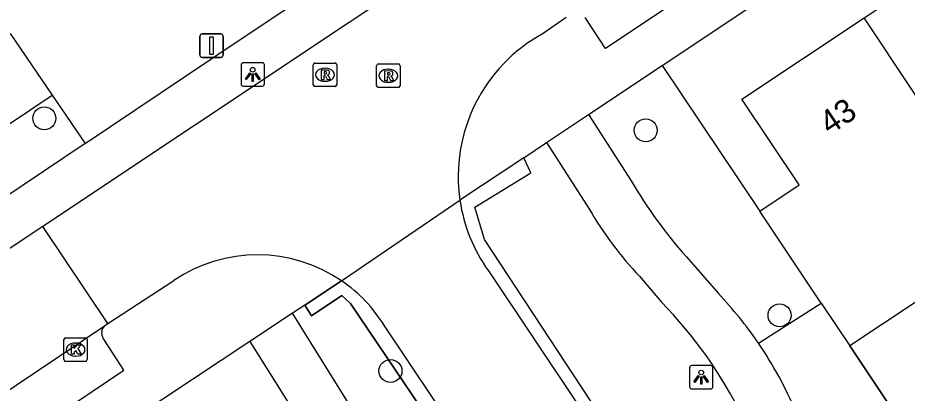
# Model space of a CAD drawing. Extents: x 158352 to 159489, y 383828 to 384597.
# Drawn here: x 158685.53 to 158723.41, y 384360.5 to 384376.52 of the extents above; entities that cross this region are included whole.
import ezdxf

# ---------------------------------------------------------------- set-up
doc = ezdxf.new("R2010")
doc.units = 0
for name, color, linetype in [('IMGEO_Boom', 7, 'Continuous'), ('IMGEO_Groenvoorziening', 7, 'Continuous'), ('IMGEO_Haag', 7, 'Continuous'), ('IMGEO_Kolk', 7, 'Continuous'), ('IMGEO_Lichtpunt', 7, 'Continuous'), ('IMGEO_Muur', 7, 'Continuous'), ('IMGEO_Pand', 7, 'Continuous'), ('IMGEO_Pand_nummerreeks', 7, 'Continuous'), ('IMGEO_Rijbaan_lokaal_open', 7, 'Continuous'), ('IMGEO_Rioolput', 7, 'Continuous'), ('IMGEO_Verkeersbordpaal', 7, 'Continuous'), ('IMGEO_Voetpad_gesloten', 7, 'Continuous'), ('IMGEO_Voetpad_open', 7, 'Continuous')]:
    doc.layers.add(name, color=color, linetype=linetype)

msp = doc.modelspace()

# ---------------------------------------------------------------- linework, layer by layer
at = {"layer": 'IMGEO_Boom'}
for centre in [(158686.653, 384372.225), (158712.272, 384371.717), (158717.972, 384363.823), (158701.4, 384361.451)]:
    msp.add_circle(centre, 0.489, dxfattribs=at)
at = {"layer": 'IMGEO_Groenvoorziening'}
for points in [[(158643.13, 384347.868), (158675.357, 384369.296), (158675.482, 384369.379), (158675.607, 384369.462), (158685.2, 384375.84), (158686.987, 384373.219)], [(158712.97, 384374.475), (158717.126, 384368.26)], [(158641.434, 384342.662), (158670.801, 384362.332), (158671.801, 384363.005), (158686.987, 384373.219)], [(158686.987, 384373.219), (158688.395, 384371.153)], [(158721.08, 384342.484), (158721.565, 384342.867), (158720.569, 384344.237), (158712.693, 384355.962), (158705.402, 384367.055), (158704.999, 384368.433), (158707.385, 384369.905), (158707.074, 384370.542)], [(158705.665, 384355.479), (158699.704, 384364.332), (158699.322, 384364.675), (158698.031, 384363.799), (158697.75, 384364.255)], [(158717.07, 384362.641), (158719.749, 384364.339)], [(158720.967, 384362.517), (158727.592, 384352.549), (158727.446, 384352.432), (158727.575, 384352.237)]]:
    msp.add_lwpolyline(points, dxfattribs=at)
at = {"layer": 'IMGEO_Haag'}
for points in [[(158707.074, 384370.542), (158704.359, 384368.731)], [(158705.57, 384365.721), (158721.08, 384342.484), (158721.565, 384342.867), (158720.569, 384344.237), (158712.693, 384355.962), (158705.402, 384367.055), (158704.999, 384368.433), (158707.385, 384369.905), (158707.074, 384370.542)], [(158699.316, 384365.295), (158697.75, 384364.255), (158698.031, 384363.799), (158699.322, 384364.675), (158699.704, 384364.332), (158713.823, 384343.363), (158716.687, 384338.771), (158717.302, 384339.096), (158716.829, 384339.908), (158701.145, 384363.368)]]:
    msp.add_lwpolyline(points, dxfattribs=at)
for centre, radius, start, end in [((158711.218, 384369.742), 6.933, 188.3835, 215.4489), ((158695.745, 384360.074), 6.326, 31.383, 55.6278)]:
    msp.add_arc(centre, radius, start, end, dxfattribs=at)
at = {"layer": 'IMGEO_Kolk'}
for p, q in [((158687.486, 384361.933), (158687.486, 384362.785)), ((158687.561, 384362.859), (158688.413, 384362.859)), ((158688.487, 384362.785), (158688.487, 384361.933)), ((158687.974, 384362.639), (158687.999, 384362.639)), ((158687.997, 384362.079), (158687.972, 384362.079)), ((158688.413, 384361.859), (158687.561, 384361.859))]:
    msp.add_line(p, q, dxfattribs=at)
for points in [[(158687.486, 384361.933), (158687.486, 384362.785)], [(158687.561, 384362.859), (158688.413, 384362.859)], [(158688.487, 384362.785), (158688.487, 384361.933)], [(158687.807, 384362.559), (158687.93, 384362.559), (158687.93, 384362.408), (158688.06, 384362.559), (158688.224, 384362.559), (158688.078, 384362.408), (158688.231, 384362.159), (158688.079, 384362.159), (158687.994, 384362.323), (158687.93, 384362.256), (158687.93, 384362.159), (158687.807, 384362.159), (158687.807, 384362.559)], [(158688.413, 384361.859), (158687.561, 384361.859)]]:
    msp.add_lwpolyline(points, dxfattribs=at)
for centre, start, end in [((158687.563, 384362.783), 91.552, 178.448), ((158687.563, 384362.783), 91.552, 178.448), ((158688.411, 384362.783), 1.552, 88.448), ((158688.411, 384362.783), 1.552, 88.448), ((158687.563, 384361.935), 181.552, 268.448), ((158687.563, 384361.935), 181.552, 268.448), ((158688.411, 384361.935), 271.552, 358.448), ((158688.411, 384361.935), 271.552, 358.448)]:
    msp.add_arc(centre, 0.0765, start, end, dxfattribs=at)
for centre, major_axis, ratio, start_param, end_param in [((158687.973, 384362.359), (-0.387, 0.002), 0.722429, 4.712389, 7.853982), ((158687.998, 384362.359), (-0.39, 0.002), 0.717154, 1.570796, 4.712389)]:
    msp.add_ellipse(centre, major_axis=major_axis, ratio=ratio, start_param=start_param, end_param=end_param, dxfattribs=at)
at = {"layer": 'IMGEO_Lichtpunt'}
for p, q in [((158695.035, 384374.502), (158695.035, 384373.695)), ((158695.035, 384374.502), (158695.035, 384373.695)), ((158695.937, 384374.597), (158695.129, 384374.597)), ((158695.937, 384374.597), (158695.129, 384374.597)), ((158696.031, 384373.695), (158696.031, 384374.502)), ((158696.031, 384373.695), (158696.031, 384374.502)), ((158695.129, 384373.601), (158695.937, 384373.601)), ((158695.129, 384373.601), (158695.937, 384373.601)), ((158714.137, 384361.586), (158714.137, 384360.779)), ((158714.137, 384361.586), (158714.137, 384360.779)), ((158715.039, 384361.681), (158714.231, 384361.681)), ((158715.039, 384361.681), (158714.231, 384361.681)), ((158715.133, 384360.779), (158715.133, 384361.586)), ((158715.133, 384360.779), (158715.133, 384361.586)), ((158714.231, 384360.685), (158715.039, 384360.685)), ((158714.231, 384360.685), (158715.039, 384360.685))]:
    msp.add_line(p, q, dxfattribs=at)
for points in [[(158695.409, 384374.166), (158695.448, 384374.138), (158695.26, 384373.876), (158695.222, 384373.903), (158695.409, 384374.166)], [(158695.511, 384374.118), (158695.558, 384374.118), (158695.558, 384373.796), (158695.511, 384373.796), (158695.511, 384374.118)], [(158695.621, 384374.138), (158695.659, 384374.165), (158695.846, 384373.903), (158695.807, 384373.875), (158695.621, 384374.138)], [(158714.511, 384361.25), (158714.55, 384361.222), (158714.362, 384360.96), (158714.324, 384360.987), (158714.511, 384361.25)], [(158714.613, 384361.202), (158714.66, 384361.202), (158714.66, 384360.88), (158714.613, 384360.88), (158714.613, 384361.202)], [(158714.723, 384361.222), (158714.761, 384361.249), (158714.948, 384360.987), (158714.909, 384360.959), (158714.723, 384361.222)]]:
    msp.add_lwpolyline(points, dxfattribs=at)
for centre in [(158695.534, 384374.3), (158714.636, 384361.384)]:
    msp.add_circle(centre, 0.0994, dxfattribs=at)
for centre, start, end in [((158695.129, 384374.502), 90, 180), ((158695.129, 384374.502), 90, 180), ((158695.937, 384374.502), 0, 90), ((158695.937, 384374.502), 0, 90), ((158695.129, 384373.695), 180, 270), ((158695.129, 384373.695), 180, 270), ((158695.937, 384373.695), 270, 0), ((158695.937, 384373.695), 270, 360), ((158714.231, 384361.586), 90, 180), ((158714.231, 384361.586), 90, 180), ((158715.039, 384361.586), 0, 90), ((158715.039, 384361.586), 0, 90), ((158714.231, 384360.779), 180, 270), ((158714.231, 384360.779), 180, 270), ((158715.039, 384360.779), 270, 0), ((158715.039, 384360.779), 270, 360)]:
    msp.add_arc(centre, 0.0946, start, end, dxfattribs=at)
at = {"layer": 'IMGEO_Muur'}
msp.add_lwpolyline([(158727.575, 384352.237), (158727.446, 384352.432), (158727.592, 384352.549), (158720.967, 384362.517)], dxfattribs=at)
at = {"layer": 'IMGEO_Pand'}
for points in [[(158721.573, 384376.51), (158726.714, 384379.933)], [(158717.126, 384368.26), (158718.813, 384369.388), (158716.368, 384373.045), (158721.573, 384376.51)], [(158727.843, 384367.089), (158721.573, 384376.51)], [(158719.749, 384364.339), (158717.126, 384368.26)], [(158727.843, 384367.089), (158720.967, 384362.517)], [(158719.749, 384364.339), (158720.967, 384362.517)]]:
    msp.add_lwpolyline(points, dxfattribs=at)
at = {"layer": 'IMGEO_Rijbaan_lokaal_open'}
for points in [[(158706.188, 384380.69), (158686.591, 384367.607)], [(158708.878, 384376.53), (158707.899, 384375.841)], [(158699.316, 384365.295), (158704.359, 384368.731)], [(158686.591, 384367.607), (158681.988, 384364.56), (158639.19, 384336.064)], [(158689.364, 384363.473), (158686.591, 384367.607)], [(158705.57, 384365.721), (158721.08, 384342.484)], [(158689.364, 384363.473), (158692.179, 384365.308)], [(158689.221, 384363.377), (158689.364, 384363.473)], [(158646.929, 384335.217), (158684.485, 384360.21), (158689.221, 384363.377)], [(158717.302, 384339.096), (158716.829, 384339.908), (158701.145, 384363.368)]]:
    msp.add_lwpolyline(points, dxfattribs=at)
for centre, radius, start, end in [((158711.228, 384369.747), 6.944, 118.6474, 188.416), ((158711.218, 384369.742), 6.933, 188.3835, 215.4489), ((158695.738, 384360.066), 6.336, 55.6168, 124.1744), ((158695.745, 384360.074), 6.326, 31.383, 55.6278)]:
    msp.add_arc(centre, radius, start, end, dxfattribs=at)
at = {"layer": 'IMGEO_Rioolput'}
for p, q in [((158698.11, 384373.66), (158698.11, 384374.512)), ((158698.185, 384374.586), (158699.037, 384374.586)), ((158699.111, 384374.512), (158699.111, 384373.66)), ((158700.81, 384373.619), (158700.81, 384374.471)), ((158700.885, 384374.545), (158701.737, 384374.545)), ((158701.811, 384374.471), (158701.811, 384373.619)), ((158698.598, 384374.366), (158698.623, 384374.366)), ((158701.298, 384374.325), (158701.323, 384374.325)), ((158698.621, 384373.806), (158698.596, 384373.806)), ((158701.321, 384373.765), (158701.296, 384373.765)), ((158699.037, 384373.586), (158698.185, 384373.586)), ((158701.737, 384373.545), (158700.885, 384373.545))]:
    msp.add_line(p, q, dxfattribs=at)
for points in [[(158698.11, 384373.66), (158698.11, 384374.512)], [(158698.185, 384374.586), (158699.037, 384374.586)], [(158699.111, 384374.512), (158699.111, 384373.66)], [(158700.81, 384373.619), (158700.81, 384374.471)], [(158700.885, 384374.545), (158701.737, 384374.545)], [(158701.811, 384374.471), (158701.811, 384373.619)], [(158698.699, 384374.284), (158698.447, 384374.286), (158698.447, 384373.886)], [(158698.625, 384374.205), (158698.571, 384374.205), (158698.571, 384374.124)], [(158698.571, 384374.124), (158698.623, 384374.124)], [(158701.399, 384374.243), (158701.147, 384374.245), (158701.147, 384373.845)], [(158701.325, 384374.164), (158701.271, 384374.164), (158701.271, 384374.083)], [(158701.271, 384374.083), (158701.323, 384374.083)], [(158698.447, 384373.886), (158698.571, 384373.886), (158698.571, 384374.048), (158698.582, 384374.048)], [(158698.629, 384374.019), (158698.7, 384373.886), (158698.84, 384373.886), (158698.775, 384374.012)], [(158701.147, 384373.845), (158701.271, 384373.845), (158701.271, 384374.007), (158701.282, 384374.007)], [(158701.329, 384373.978), (158701.4, 384373.845), (158701.54, 384373.845), (158701.475, 384373.971)], [(158699.037, 384373.586), (158698.185, 384373.586)], [(158701.737, 384373.545), (158700.885, 384373.545)]]:
    msp.add_lwpolyline(points, dxfattribs=at)
for centre, radius, start, end in [((158698.187, 384374.51), 0.0765, 91.552, 178.448), ((158698.187, 384374.51), 0.0765, 91.552, 178.448), ((158699.035, 384374.51), 0.0765, 1.552, 88.448), ((158699.035, 384374.51), 0.0765, 1.552, 88.448), ((158700.887, 384374.469), 0.0765, 91.552, 178.448), ((158700.887, 384374.469), 0.0765, 91.552, 178.448), ((158701.735, 384374.469), 0.0765, 1.552, 88.448), ((158701.735, 384374.469), 0.0765, 1.552, 88.448), ((158698.607, 384374.313), 0.19, 274.7715, 282.9687), ((158698.631, 384374.109), 0.0964, 77.0061, 93.1865), ((158698.645, 384374.166), 0.0378, 276.6634, 79.6772), ((158698.698, 384374.174), 0.109, 350.3612, 89.416), ((158698.696, 384374.174), 0.112, 277.5842, 350.9817), ((158701.307, 384374.272), 0.19, 274.7715, 282.9687), ((158701.331, 384374.068), 0.0964, 77.0061, 93.1865), ((158701.345, 384374.125), 0.0378, 276.6634, 79.6772), ((158701.398, 384374.133), 0.109, 350.3612, 89.416), ((158701.396, 384374.133), 0.112, 277.5842, 350.9817), ((158698.581, 384373.995), 0.0533, 26.0293, 88.6989), ((158698.68, 384373.959), 0.108, 29.5134, 73.7905), ((158701.281, 384373.954), 0.0533, 26.0293, 88.6989), ((158701.38, 384373.918), 0.108, 29.5134, 73.7905), ((158698.187, 384373.662), 0.0765, 181.552, 268.448), ((158698.187, 384373.662), 0.0765, 181.552, 268.448), ((158699.035, 384373.662), 0.0765, 271.552, 358.448), ((158699.035, 384373.662), 0.0765, 271.552, 358.448), ((158700.887, 384373.621), 0.0765, 181.552, 268.448), ((158700.887, 384373.621), 0.0765, 181.552, 268.448), ((158701.735, 384373.621), 0.0765, 271.552, 358.448), ((158701.735, 384373.621), 0.0765, 271.552, 358.448)]:
    msp.add_arc(centre, radius, start, end, dxfattribs=at)
for centre, major_axis, ratio, start_param, end_param in [((158698.597, 384374.086), (-0.387, 0.002), 0.722429, 4.712389, 7.853982), ((158698.622, 384374.086), (-0.39, 0.002), 0.717154, 1.570796, 4.712389), ((158701.297, 384374.045), (-0.387, 0.002), 0.722429, 4.712389, 7.853982), ((158701.322, 384374.045), (-0.39, 0.002), 0.717154, 1.570796, 4.712389)]:
    msp.add_ellipse(centre, major_axis=major_axis, ratio=ratio, start_param=start_param, end_param=end_param, dxfattribs=at)
at = {"layer": 'IMGEO_Verkeersbordpaal'}
for p, q in [((158693.282, 384374.927), (158693.282, 384375.727)), ((158693.282, 384375.727), (158693.282, 384374.927)), ((158693.382, 384375.827), (158694.172, 384375.827)), ((158694.172, 384375.827), (158693.382, 384375.827)), ((158694.272, 384375.727), (158694.272, 384374.927)), ((158694.272, 384374.927), (158694.272, 384375.727)), ((158694.172, 384374.827), (158693.382, 384374.827)), ((158693.382, 384374.827), (158694.172, 384374.827))]:
    msp.add_line(p, q, dxfattribs=at)
msp.add_lwpolyline([(158693.702, 384375.702), (158693.852, 384375.702), (158693.852, 384374.952), (158693.702, 384374.952), (158693.702, 384375.702)], dxfattribs=at)
for centre, start, end in [((158693.382, 384375.727), 90, 180), ((158693.382, 384375.727), 90, 180), ((158694.172, 384375.727), 0, 90), ((158694.172, 384375.727), 360, 90), ((158693.382, 384374.927), 180, 270), ((158693.382, 384374.927), 180, 270), ((158694.172, 384374.927), 270, 0), ((158694.172, 384374.927), 270, 0)]:
    msp.add_arc(centre, 0.1, start, end, dxfattribs=at)
at = {"layer": 'IMGEO_Voetpad_gesloten'}
for points in [[(158708.044, 384371.19), (158709.84, 384372.387)], [(158709.84, 384372.387), (158711.653, 384369.562)], [(158708.044, 384371.19), (158709.873, 384368.34)], [(158714.002, 384366.316), (158715.365, 384364.748)], [(158712.009, 384365.488), (158712.94, 384364.388)], [(158697.233, 384363.912), (158695.416, 384362.705)], [(158701.74, 384356.644), (158697.233, 384363.912)], [(158695.416, 384362.705), (158700.493, 384354.599)]]:
    msp.add_lwpolyline(points, dxfattribs=at)
for centre, radius, start, end in [((158729.547, 384380.038), 20.735, 210.3471, 221.4364), ((158723.329, 384376.192), 15.58, 210.265, 223.3976), ((158703.198, 384353.159), 16.803, 34.354, 43.6061), ((158699.629, 384351.337), 18.641, 26.0267, 44.4344), ((158703.138, 384353.15), 16.857, 22.9533, 34.2649)]:
    msp.add_arc(centre, radius, start, end, dxfattribs=at)
at = {"layer": 'IMGEO_Voetpad_open'}
for points in [[(158688.395, 384371.153), (158694.831, 384375.482), (158698.179, 384377.716), (158704.964, 384382.243), (158707.798, 384384.134), (158715.642, 384389.377), (158716.954, 384390.243), (158742.278, 384407.217), (158743.282, 384407.89), (158756.032, 384416.448), (158759.672, 384418.896), (158801.455, 384446.936), (158826.388, 384463.558), (158848.997, 384478.808), (158860.431, 384486.52), (158863.532, 384488.47)], [(158747.129, 384401.534), (158748.032, 384400.223), (158710.556, 384375.208), (158709.691, 384376.522)], [(158712.97, 384374.475), (158753.174, 384401.294)], [(158709.84, 384372.387), (158712.97, 384374.475)], [(158688.395, 384371.153), (158673.196, 384360.93), (158672.19, 384360.253), (158640.109, 384338.766)], [(158707.074, 384370.542), (158708.044, 384371.19)], [(158707.074, 384370.542), (158704.359, 384368.731)], [(158697.75, 384364.255), (158699.316, 384365.295)], [(158697.75, 384364.255), (158697.233, 384363.912)], [(158647.518, 384335.038), (158648.374, 384333.728), (158686.654, 384359.199), (158690.04, 384361.478), (158689.167, 384362.842)], [(158695.416, 384362.705), (158690.486, 384359.432)]]:
    msp.add_lwpolyline(points, dxfattribs=at)
msp.add_arc((158689.523, 384363.076), 0.426, 135.1358, 213.337, dxfattribs=at)

# ---------------------------------------------------------------- texts
at = {"layer": 'IMGEO_Pand_nummerreeks'}
msp.add_text('43', height=1, rotation=33.6498, dxfattribs=at).set_placement((158720.103, 384371.494))

doc.saveas('drawing.dxf')
